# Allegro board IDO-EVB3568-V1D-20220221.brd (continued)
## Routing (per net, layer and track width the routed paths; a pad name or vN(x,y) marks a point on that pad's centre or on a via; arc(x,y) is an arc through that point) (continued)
USB2_HOST3_DM: length 39.3
  TOP w0.127: v2(71.75,67.19) 72,67.44 77.24,67.44 78.15,66.52 93.91,66.52 95,67.61 95.18,67.61 95.55,67.24 M5.101 ; L7.2 v2(72.94,79.18)
  BOTTOM w0.127: v2(71.75,67.19) 72,67.44 72.37,67.44 72.67,67.74 72.67,74.01 73.51,74.85 73.51,77.78 72.94,78.34 v2(72.94,79.18)
USB2_HOST3_DM_: length 14.8
  TOP w0.127: L7.3 72.94,81.59 72.67,81.86 72.67,82.32 72.83,82.49 72.83,82.91 72.96,83.04 D18.2 D18.9 72.96,84.91 72.83,85.03 72.83,85.41 72.16,86.08 70.38,86.08 68.33,88.13 68.33,89.31 68.78,89.76 69.27,89.76 70.84,91.34 J8.2
USB2_HOST3_DP: length 39.3
  TOP w0.127: v2(71.75,67.94) 72,67.69 77.34,67.69 78.26,66.78 91.77,66.78 91.9,66.9 92.28,66.9 92.41,66.78 92.79,66.78 92.91,66.9 93.29,66.9 93.42,66.78 93.8,66.78 94.89,67.86 95.18,67.86 95.55,68.24 M5.102 ; L7.1 72.14,79.27 72.2,79.21 v2(72.2,79.14)
  BOTTOM w0.127: v2(71.75,67.94) 72,67.69 72.26,67.69 72.42,67.84 72.42,74.12 73.25,74.96 73.25,77.67 72.64,78.28 72.64,78.69 v2(72.2,79.14)
USB2_HOST3_DP_: length 14.8
  TOP w0.127: J8.3 69.79,91.34 70.05,91.08 70.05,90.9 69.16,90.02 68.68,90.02 68.07,89.41 68.07,88.03 70.27,85.83 72.06,85.83 72.58,85.3 72.58,85.03 72.46,84.91 D18.10 D18.1 72.46,83.04 72.58,82.91 72.58,82.59 72.42,82.43 72.42,81.86 72.14,81.59 L7.4
USB3_HOST1_DM: length 45.8
  TOP w0.127: M5.182 36.46,47.24 36.83,46.86 37.09,46.86 38.23,48.01 38.23,50.04 39.24,51.05 47.7,51.05 48.01,50.75 48.01,50.41 v2(48.25,50.16)
  BOTTOM w0.127: v2(48.25,50.16) 48.01,50.41 48.01,76.48 49.04,77.51 L6.1
USB3_HOST1_DM_: length 10.4
  BOTTOM w0.127: L6.4 49.04,81.01 48.77,81.28 48.77,81.88 48.63,82.02 48.63,82.31 48.75,82.43 D15.6 D15.5 48.75,84.3 48.63,84.42 48.63,85.49 49.65,86.51 49.65,87.82 49.85,88.02 49.85,88.12 50.29,88.56 50.38,88.56 50.72,88.89 50.72,89.18 50.85,89.31 J5.11
USB3_HOST1_DP: length 45.8
  TOP w0.127: M5.183 36.46,46.24 36.83,46.61 37.19,46.61 38.48,47.9 38.48,49.93 39.35,50.8 47.6,50.8 47.75,50.64 47.75,50.41 v2(47.51,50.16)
  BOTTOM w0.127: v2(47.51,50.16) 47.75,50.41 47.75,76.58 48.79,77.62 48.79,78.57 48.74,78.62 48.74,78.62 48.69,78.66 48.44,78.66 48.24,78.86 L6.2
USB3_HOST1_DP_: length 10.4
  BOTTOM w0.127: L6.3 48.24,81.01 48.51,81.28 48.51,81.78 48.37,81.92 48.37,82.31 48.25,82.43 D15.7 D15.4 48.25,84.3 48.37,84.42 48.37,85.6 49.39,86.62 49.39,87.92 49.59,88.12 49.59,88.22 50.18,88.81 50.28,88.81 50.47,89 50.47,89.18 50.34,89.31 J5.12
USB3_HOST1_SSRXN: length 46.3
  TOP w0.127: R32.1 44.58,80.21 44.66,80.14 ; M5.185 36.11,44.24 36.27,44.4 36.91,44.4 39.88,47.37 46.08,47.37 v2(46.33,47.13) ; 44.66,80.14 C50.2 ; 44.66,80.14 44.78,80.01 v2(44.81,80.01)
  BOTTOM w0.127: v2(44.81,80.01) 44.96,79.86 44.96,76.96 45.59,76.33 45.59,47.62 45.84,47.37 46.08,47.37 v2(46.33,47.13)
USB3_HOST1_SSRXN_: length 9.6
  TOP w0.127: J5.14 47.34,87.81 47.47,87.68 47.47,86.74 46.96,86.23 45.47,86.23 44.82,85.59 44.82,84.37 44.7,84.25 D17.7 D17.4 44.7,82.63 44.88,82.45 44.88,81.51 R32.2
USB3_HOST1_SSRXP: length 46.3
  TOP w0.127: v2(46.33,47.87) 46.08,47.62 39.77,47.62 36.8,44.65 36.35,44.65 35.76,45.24 M5.184 ; R33.1 45.36,80.11 v2(45.36,80.01) 45.49,80.14 C51.2
  BOTTOM w0.127: v2(45.36,80.01) 45.21,79.86 45.21,77.07 45.85,76.43 45.85,47.73 45.95,47.62 46.08,47.62 v2(46.33,47.87)
USB3_HOST1_SSRXP_: length 9.6
  TOP w0.127: J5.15 47.85,87.81 47.72,87.68 47.72,86.64 47.07,85.98 45.57,85.98 45.07,85.48 45.07,84.37 45.2,84.25 D17.6 D17.5 45.2,82.53 45.14,82.47 45.14,81.66 R33.2
USB3_HOST1_SSTXN: length 49
  TOP w0.127: M5.181 35.79,48.24 36.16,48.61 36.7,48.61 37.34,49.25 37.34,50.55 38.81,52.02 49.5,52.02 49.81,51.71 49.81,51.4 v2(49.56,51.16)
  BOTTOM w0.127: v2(49.56,51.16) 49.73,51.16 50.05,51.48 50.05,75.94 53.54,79.43 53.54,80.57 53.31,80.8 C40.1
USB3_HOST1_SSTXN_: length 7.3
  BOTTOM w0.127: C40.2 53.47,82.01 53.47,82.42 53.23,82.66 D16.7 D16.4 53.23,84.3 53.35,84.42 53.35,86.35 53.47,86.47 53.47,87.68 53.34,87.81 J5.17
USB3_HOST1_SSTXP: length 49
  TOP w0.127: M5.180 35.8,49.24 36.18,48.86 36.59,48.86 37.08,49.36 37.08,50.65 38.71,52.27 49.61,52.27 50.06,51.82 50.06,51.4 v2(50.31,51.16)
  BOTTOM w0.127: v2(50.31,51.16) 50.31,75.83 53.8,79.32 53.8,80.42 C42.1
USB3_HOST1_SSTXP_: length 7.3
  BOTTOM w0.127: J5.18 53.85,87.81 53.72,87.68 53.72,86.36 53.61,86.25 53.61,84.42 53.73,84.3 D16.5 D16.6 53.73,82.01 54.08,81.66 C42.2
USB3_OTG0_DM: length 49.5
  TOP w0.127: M5.188 36.46,41.24 36.83,40.86 37.18,40.86 41.4,45.09 47.51,45.09 v2(47.75,45.33)
  BOTTOM w0.127: L5.1 47.26,78.66 47.07,78.46 46.84,78.46 46.72,78.33 46.72,77.8 47.07,77.45 47.07,45.21 47.22,45.06 47.48,45.06 v2(47.75,45.33)
USB3_OTG0_DM_: length 14.3
  BOTTOM w0.127: L5.4 47.26,81.36 46.99,81.64 46.99,81.92 47.13,82.06 47.13,82.55 47.25,82.67 D15.9 D15.2 47.25,84.3 47.13,84.42 47.13,86.25 47.75,86.87 47.75,88.39 48.49,89.13 48.49,89.26 49.6,90.37 49.6,91.15 50.2,91.75 50.38,91.75 50.72,92.09 50.72,92.38 50.85,92.51 J5.2
USB3_OTG0_DP: length 49.5
  TOP w0.127: M5.189 36.46,40.24 36.83,40.61 37.29,40.61 41.51,44.83 47.51,44.83 v2(47.75,44.59)
  BOTTOM w0.127: L5.2 46.46,77.69 46.81,77.34 46.81,45.11 47.11,44.81 47.53,44.81 v2(47.75,44.59)
USB3_OTG0_DP_: length 14.3
  BOTTOM w0.127: J5.3 50.34,92.51 50.47,92.38 50.47,92.2 50.28,92.01 50.1,92.01 49.35,91.26 49.35,90.47 48.23,89.36 48.23,89.23 47.5,88.5 47.5,86.97 46.88,86.35 46.88,84.42 46.75,84.3 D15.1 D15.10 46.75,82.67 46.88,82.54 46.88,82.16 46.74,82.02 46.74,81.64 46.46,81.36 L5.3
USB3_OTG0_SSRXN: length 50.9
  TOP w0.127: v2(42.66,79.91) 42.66,80.22 R30.1 ; v2(45.72,43.44) 45.48,43.69 42.04,43.69 36.96,38.61 36.59,38.61 36.22,38.24 M5.191
  BOTTOM w0.127: v2(45.72,43.44) 45.48,43.69 45.09,43.69 44.7,44.07 44.7,75.31 42.66,77.35 v2(42.66,79.91)
USB3_OTG0_SSRXN_: length 16.9
  TOP w0.127: R30.2 42.93,81.58 43.18,81.58 43.43,81.84 43.43,82.37 43.2,82.61 D17.1 D17.10 43.2,84.14 43.44,84.39 43.44,86.07 41.76,87.75 41.76,89.97 42.87,91.08 45.57,91.08 46.24,91.75 46.71,91.75 46.89,91.58 46.89,91.19 46.71,91.01 J5.5
USB3_OTG0_SSRXP: length 50.8
  TOP w0.127: v2(45.72,44.19) 45.48,43.94 41.93,43.94 36.85,38.86 36.59,38.86 36.22,39.24 M5.190 ; R31.1 43.41,80.19 v2(43.41,79.91)
  BOTTOM w0.127: v2(43.41,79.91) 43.21,79.71 43.05,79.71 42.92,79.58 42.92,77.46 44.96,75.42 44.96,44.17 45.19,43.94 45.48,43.94 v2(45.72,44.19)
USB3_OTG0_SSRXP_: length 17
  TOP w0.127: J5.6 47.8,91.01 47.04,90.25 46.2,90.25 45.62,90.83 42.98,90.83 42.01,89.87 42.01,87.86 43.7,86.17 D17.9 D17.2 43.7,81.72 43.56,81.58 R31.2
USB3_OTG0_SSTXN: length 52.6
  TOP w0.127: M5.187 36.22,42.24 36.59,42.61 37.02,42.61 40.64,46.23 48.64,46.23 48.9,45.97 48.9,45.71 v2(48.65,45.47)
  BOTTOM w0.127: v2(48.65,45.47) 48.9,45.71 48.9,76.45 51.51,79.07 51.51,80.21 51.28,80.44 51.11,80.44 C36.1
USB3_OTG0_SSTXN_: length 11.6
  BOTTOM w0.127: J5.8 53.34,91.01 53.47,90.88 53.47,90.12 51.56,88.21 51.56,87.03 51.85,86.74 51.85,84.42 51.73,84.3 D16.1 D16.10 51.73,82.54 50.85,81.66 C36.2
USB3_OTG0_SSTXP: length 52.6
  TOP w0.127: M5.186 36.22,43.24 36.59,42.86 36.92,42.86 40.53,46.48 48.75,46.48 49.15,46.08 49.15,45.71 v2(49.39,45.47)
  BOTTOM w0.127: v2(49.39,45.47) 49.15,45.71 49.15,76.35 51.77,78.96 C37.1
USB3_OTG0_SSTXP_: length 11.5
  BOTTOM w0.127: J5.9 53.85,91.01 53.72,90.88 53.72,90.01 51.82,88.11 51.82,87.14 52.11,86.85 52.11,84.42 52.23,84.3 D16.2 D16.9 52.23,82.69 51.54,82 51.54,81.82 51.7,81.66 C37.2
USB3_OTG0_VBUSDET: length 63.9
  TOP w0.127: v1(48.11,42.42) 41.91,42.42 36.73,37.24 M5.192 ; v2(55.75,80.14) 56.39,79.5 61.25,79.5 v2(61.95,80.21)
  BOTTOM w0.127: v1(48.11,42.42) 51.05,45.37 51.05,72.01 54.94,75.9 54.94,78.16 55.75,78.97 v2(55.75,80.14) ; v2(61.95,80.21) 61.95,80.29 61.98,80.32 61.98,80.72 R29.1
  BOTTOM w0.305: R29.1 R28.1
USB_OTG_PWREN_H: length 87.3
  TOP w0.127: v1(67.74,80.98) 68.07,80.64 68.07,75.69 68.45,75.31 70.31,75.31 70.68,74.94 72.63,74.94 73.15,74.42 88.49,74.42 89.26,73.66 94.03,73.66 99.57,68.12 99.57,62.99 100.97,61.59 100.97,53.59 102.36,52.2 102.36,49.78 97.54,44.96 97.54,44.2 97.92,43.81 97.92,33.4 97.28,32.77 97.28,27.69 96.83,27.24 M5.61
  BOTTOM w0.203: R34.1 66.37,80.98 U4.4
  BOTTOM w0.305: v1(67.74,80.98) 67.18,80.98 R34.1
VOLN: length 19.9
  TOP w0.381: J17.4 107.64,7.37 ; 107.64,7.37 107.26,7.75 v2(106.68,7.75) ; 107.64,7.37 107.64,9.09 108.33,9.78 108.33,11 D46.1 108.05,11.28 108.34,11.57 108.34,11.98 v2(108.18,12.14)
  BOTTOM w0.381: TP27.1 106.17,7.75 v2(106.68,7.75) ; v2(108.18,12.14) 108.36,11.97 108.36,11.4 108.84,10.92 109.88,10.92 110.52,11.56 110.52,14.33 109.66,15.18 108.22,15.18 C87.1 107.68,15.18 107.29,15.18 L17.2
VOLP: length 17.6
  TOP w0.381: v2(109.04,12.14) 108.85,11.95 108.85,11.6 D45.1 108.84,10.94 108.84,9.88 109.64,9.08 109.64,6.94 ; J17.3 109.64,6.94 ; 109.64,6.94 v2(108.84,7.75)
  BOTTOM w0.381: v2(108.84,7.75) 108.2,7.75 TP26.1 ; v2(109.04,12.14) 108.86,11.97 108.86,11.62 109.05,11.43 109.67,11.43 110.01,11.77 110.01,14.12 109.45,14.67 108.22,14.67 C88.1 107.68,14.67 107.29,14.67 L18.2
VORN: length 24.4
  TOP w0.381: 111.64,6.73 111.26,7.11 v2(110.74,7.11) ; 111.64,6.73 J17.2 ; 111.64,6.73 111.64,9.03 112.45,9.83 112.45,11.02 D44.1 112.43,11.52 112.43,12.01 v2(112.27,12.18)
  BOTTOM w0.381: TP25.1 108.97,5.33 v2(110.74,7.11) ; v2(112.27,12.18) 112.42,12.33 112.42,15.39 109.44,18.36 108.18,18.36 C90.1 107.72,18.36 107.25,18.36 L19.2
VORP: length 28.1
  TOP w0.381: J17.1 113.64,6.77 ; 113.64,6.77 113.3,7.11 v2(112.78,7.11) ; 113.64,6.77 113.64,9.17 112.95,9.86 112.95,11.02 D43.1 112.94,11.55 112.94,11.99 v2(113.13,12.18)
  BOTTOM w0.381: v2(112.78,7.11) 111.51,7.11 107.7,3.3 TP24.1 ; v2(113.13,12.18) 112.93,12.38 112.93,15.6 111.7,16.83 109.65,18.87 108.13,18.87 C91.1 107.82,18.92 107.2,18.92 L20.2
WIFI1T1R_CLK: length 20.2
  TOP w0.127: v2(112.01,62.71) 112.01,60.96 111.4,60.35 U23.17
  BOTTOM w0.127: R159.2 C153.2 101.17,57.66 108.08,57.66 109.83,59.41 109.83,59.97 109.73,60.07 109.22,60.07 109.09,60.2 109.09,60.45 109.22,60.58 109.73,60.58 109.82,60.67 109.82,61.18 111.35,62.71 v2(112.01,62.71)
WIFI1T1R_CMD: length 2.7
  TOP w0.127: R158.2 113.13,61.44 112.3,60.62 U23.16
WIFI1T1R_D0: length 2.7
  TOP w0.127: R153.2 110.74,61.72 111,61.47 111,60.71 110.5,60.21 U23.18
WIFI1T1R_D1: length 2.4
  TOP w0.127: U23.19 109.6,61.08 109.6,61.09 R154.2
WIFI1T1R_D2: length 3
  TOP w0.127: U23.14 114.1,60.94 R155.2
WIFI1T1R_D3: length 2.9
  TOP w0.127: U23.15 113.2,61.11 R156.2
WIFI1T1R_XTAL_IN: length 9.5
  TOP w0.203: XT3.3 120.85,62.2 120.85,59.92 C155.1 120.62,58.47 118.36,58.47 117.75,57.85 U23.10
WIFI1T1R_XTAL_OUT: length 3.4
  TOP w0.203: R163.2 119.76,58.83 118.18,58.83 118.11,58.75 U23.11
WIFI_REG_ON_H_GPIO3_D4: length 31.3
  TOP w0.127: R182.1 102.62,49.99 102.62,52.32 101.47,53.47 v2(101.47,53.95) ; v2(116.2,63.12) 116.3,63.22 R168.1 ; M5.91 96.81,57.24 100.1,53.95 v2(100.2,53.95)
  BOTTOM w0.127: v2(116.2,63.12) 116.2,62.74 108.71,55.24 104.52,55.24 103.38,54.1 102.11,54.1 101.96,53.95 v2(101.47,53.95) v2(100.2,53.95)
WIFI_WAKE_HOST_H_GPIO3_D5: length 23.9
  TOP w0.127: M5.90 97.23,56.24 v2(99.53,53.94) ; U23.13 v2(115,60.9)
  BOTTOM w0.127: v2(99.53,53.94) 99.93,53.54 102.06,53.54 102.36,53.85 103.5,53.85 104.65,54.99 108.97,54.99 114.88,60.9 v2(115,60.9)
WIFIBT_32KIN_1T1R: length 37.2
  TOP w0.127: U23.24 104.97,57.85 104.06,56.94 R176.2 C168.2 103.58,55.4 103.15,55.4 v2(102.87,55.12) ; R177.2 v2(113.28,43.54)
  BOTTOM w0.127: v2(102.87,55.12) 102.36,54.61 97.28,54.61 96.77,54.1 96.77,46.86 97.41,46.23 97.92,46.23 99.19,44.96 111.86,44.96 v2(113.28,43.54)
N17052705: length 1.5
  TOP w0.381: R179.1 104.23,53.35 U23.29
N17052995: length 4.9
  TOP w0.127: R181.2 104.04,49.43 R182.2 104.49,49.4 104.74,49.15 105.87,49.15 106.46,48.55 U23.34
N17053074: length 3.4
  TOP w0.508: C154.2 C156.2 U23.2
N17053234: length 2.6
  TOP w0.508: J29.2 C157.2 C154.1
N17053374: length 2.4
  TOP w0.127: R163.1 120.22,60.2 C158.2 119.2,60.5 119.02,60.68 XT3.1
N17846666: length 12
  TOP w0.127: v2(102.53,69.2) 102.13,69.6 102.13,70.97 98.3,74.8 98.3,76.76 R215.1
  BOTTOM w0.127: v2(102.53,69.2) 102.68,69.05 103.32,69.05 103.34,69.07 U24.31
N67123537: length 1.3
  BOTTOM w0.203: U4.3 66.06,84 R35.1
N67146313: length 8
  BOTTOM w0.254: R46.1 76.96,55.63 77.47,56.13 80.13,56.13 ; 80.13,56.13 80.9,56.13 81.13,56.37 U8.43 ; 80.13,56.13 U8.45
N67159131: length 1.5
  BOTTOM w0.127: R41.1 72.24,83.67 U6.3
N67228398: length 1.3
  TOP w0.305: C2.2 65,81.34 U1.4
N67228404: length 3.4
  TOP w0.254: R6.1 C8.1 ; C8.1 65.75,83.57 65.36,83.18 U1.6 ; C8.1 R4.2
N67928236: length 1.9
  TOP w0.381: U26.1 12.89,70.25 12.75,70.38 C218.2
N67928238: length 2.2
  TOP w0.381: C218.1 11.43,69.33 11.81,68.95 U26.3
N67928242: length 1.9
  TOP w0.381: U26.4 11.53,68.3 C219.2
N67928244: length 1.9
  TOP w0.381: C219.1 11.53,67.65 U26.5
N67928270: length 1.6
  TOP w0.127: U26.2 v2(14.22,69.6)
  BOTTOM w0.254: C220.2 13.76,69.6 v2(14.22,69.6)
N67928274: length 2.1
  TOP w0.381: C221.2 12.01,67 U26.6
N68112138: length 1.3
  TOP w0.381: R37.1 48.48,83.61 U5.3
N68117516: length 10.3
  TOP w0.127: R27.2 104.08,20.4 104.48,20.8 D12.1 106.93,20.8 108.94,18.8 111.76,18.8 112.01,18.54 J4.2
N68117520: length 6
  TOP w0.127: D10.C 105.42,18.28 106.02,17.68 D11.1 106.43,17.68 J4.1
N68117689: length 2.9
  TOP w0.127: D10.A 104.33,20.08 R26.2 R25.2
N68120764: length 6.9
  TOP w0.508: R84.1 v1(34.42,87.38) R82.1 ; D49.C v1(38.73,85.98)
  BOTTOM w0.508: v1(34.42,87.38) 35.81,85.98 v1(38.73,85.98)
N68141872: length 1.4
  BOTTOM w0.508: R115.1 40.71,31.24 40.74,31.26 U16.3
N68149060: length 2.9
  TOP w0.127: R62.2 142.16,99.19 SW1.1
N68226715: length 3.3
  TOP w0.127: U26.14 18.15,68.95 18.03,68.83 v2(17.65,68.83)
  BOTTOM w0.203: L34.1 17.02,68.2 v2(17.65,68.83)
N68226717: length 3.4
  TOP w0.127: v2(17.02,68.83) 17.56,68.3 U26.13
  BOTTOM w0.203: L35.1 16.74,68.83 v2(17.02,68.83)
N68226719: length 2
  TOP w0.203: U26.7 v2(14.27,66.34)
  BOTTOM w0.203: L36.1 14.81,66.34 v2(14.27,66.34)
N68226721: length 2
  TOP w0.203: U26.8 v2(14.32,65.69)
  BOTTOM w0.203: v2(14.32,65.69) 14.85,65.69 L37.1
N68234263: length 10.3
  TOP w0.254: J15.3 104.14,7.74 D38.1 104.09,13.67 R76.2
N68234265: length 5.8
  TOP w0.254: v2(95.41,10.03) 95.41,9.55 95.15,9.3 J15.2
  BOTTOM w0.254: 93.37,10.95 93.37,10.64 93.98,10.03 v2(95.41,10.03) ; 93.37,10.95 93.66,10.95 93.71,11 R73.2 ; 93.37,10.95 D40.1
N68234885: length 2.2
  TOP w0.254: C80.2 R68.2 R69.1
N68235937: length 4.1
  TOP w0.254: J15.5 95.25,12.75 D39.1 95.3,13.9 R74.2
N68290667: length 2.4
  BOTTOM w0.381: U13.1 104.09,14.43 104.37,14.71 104.81,14.71 L18.1
N68290669: length 5.1
  BOTTOM w0.381: U13.3 101.55,14.43 102.36,15.24 104.91,15.24 L17.1
N68290717: length 5
  BOTTOM w0.381: L19.1 104.96,18.29 102.49,18.29 101.55,19.23 U13.14
N68290719: length 2.2
  BOTTOM w0.381: L20.1 104.89,18.92 104.39,18.92 104.09,19.23 U13.16
N68290721: length 1
  BOTTOM w0.254: C86.1 R79.1
N68290723: length 1.9
  BOTTOM w0.254: R79.2 96.52,12.35 96.47,12.4 U13.7
N68290736: length 1.1
  TOP w0.254: R80.1 C89.1
N68290738: length 7
  TOP w0.254: R80.2 100.58,14.63 v2(96.9,18.31)
  BOTTOM w0.254: v2(96.9,18.31) 96.47,18.75 U13.10
N68290823: length 1.7
  TOP w0.254: v2(94.49,13.21) 94.11,13.59 C85.2
  BOTTOM w0.254: v2(94.49,13.21) 95,13.72 U13.8
N68391184: length 1.6
  BOTTOM w0.508: U2.1 32.59,49.51 32.77,49.68 R14.2
N68391239: length 3.6
  BOTTOM w0.508: C19.1 R12.2 R15.1 29.72,49.68 29.89,49.51 U2.5
N68444772:
  vias: v1(14.35,83.67) v1(14.35,83.01) v1(14.99,83.67) v1(14.99,82.98) v1(15.72,83.67) v1(15.75,82.96) v1(16.48,82.58) v1(17.02,82.58) v1(17.78,83.64) v1(17.81,82.91)
N68540703: length 37.4
  TOP w0.127: v2(113.85,67.37) 113.57,67.65 113.57,67.66 113.03,68.2 113.03,73.68 111.66,75.06 103.3,75.06 101.98,76.38 v2(101.98,76.48)
  BOTTOM w0.127: U25.31 117.73,67.39 117.65,67.31 114.93,67.31 114.87,67.37 v2(113.85,67.37) ; v2(101.98,76.48) 101.5,76.96 97.66,76.96 96.39,75.69 96.39,70.48 95.12,69.22 R262.1
N68550545: length 3
  TOP w0.305: U17.11 27.95,24.81 C129.2
  TOP w0.381: C126.2 C129.2
N68551303: length 3.6
  TOP w0.127: U17.8 26.68,23.31 27.08,22.91 27.08,21.87 27.64,21.31 R121.2
N68551306: length 2.3
  TOP w0.127: R122.2 27.62,25.31 U17.12
N68551396: length 3.6
  TOP w0.127: R120.2 26.72,21.67 26.72,22.48 26.39,22.81 U17.7
N68552374: length 7.2
  TOP w0.508: R131.2 R129.2 45.54,13.76 45.27,14.03 C141.1 43.37,14.03 42.55,13.21 41.59,13.21 41.09,12.7 Q9.1
N68552446: length 1.8
  TOP w0.254: R131.1 47.5,12.91 47.87,12.54 Q10.3
N68558276: length 1.1
  TOP w0.305: U15.3 12.65,22.84 R104.1
N68563618: length 5
  TOP w0.203: U34.1 123.63,41.34 C239.1 124.06,41.53 125.48,41.53 125.68,41.33 XT6.1
N68563661: length 5
  TOP w0.203: U34.2 123.4,41.99 C240.1 124.11,41.99 125.43,41.99 125.68,42.24 XT6.2
N68582360: length 14.8
  TOP w0.127: Q6.1 79.17,13.02 78.74,13.45 78.74,15.75 79.38,16.38 83.95,16.38 84.71,15.62 R90.2 85.58,14.4 C111.1 85.98,15.36 86.41,15.8 R91.2
N68582430: length 1.8
  TOP w0.381: R91.1 87.25,14.19 87.47,13.97 Q7.3
N68600227: length 4.4
  TOP w0.127: R326.1 111.86,37.29 111.28,36.7 110.62,36.7 109.45,35.54 J41.10
N68600229: length 5.2
  TOP w0.127: J41.12 110.25,35.45 111,36.2 112.62,36.2 113.28,36.86 R327.1
N68600231: length 4.1
  TOP w0.127: J41.14 111.05,35.36 111.38,35.69 v2(112.14,35.69)
  BOTTOM w0.127: v2(112.14,35.69) 112.53,35.69 112.9,35.32 R329.1
N68600309: length 2.8
  TOP w0.381: J41.8 108.65,37.01 L48.1
N68610828: length 1.5
  TOP w0.381: Q12.1 125.51,58.61 125.43,58.52 R178.2
N68611164: length 2.3
  TOP w0.254: R178.1 126.96,57.78 127.64,57.11 Q13.3
N68644173: length 2.7
  TOP w0.127: R168.2 115.9,61.52 U23.12
N68693421: length 1.4
  TOP w0.381: U7.3 76.72,80.96 76.71,80.98 R43.1
N68696061: length 1.6
  BOTTOM w0.381: R49.1 89.84,79.62 U9.3
N68696295: length 1.4
  TOP w0.381: R53.1 92.53,78.02 U10.3
N68706836: length 1.6
  TOP w0.127: R57.1 137.08,47.67 136.73,47.32 U11.3
N68707388: length 1.6
  TOP w0.203: R59.1 137.94,66.5 137.83,66.61 U12.3
N68721096: length 3.9
  TOP w0.127: v2(111.89,32.89) 110.44,31.45 U36.66
  BOTTOM w0.127: R325.2 v2(111.89,32.89)
N68721887: length 1.7
  TOP w0.254: R342.2 106.17,42.16 106.75,41.59 U37.1
N68721933: length 3.3
  TOP w0.381: R340.2 C265.1 109.5,42.62 R341.1 109.55,42.65 109.66,42.54 U37.5
N68723170: length 4.3
  TOP w0.305: v2(125.94,31.62) 125.74,31.62 125.44,31.32 U36.6
  BOTTOM w0.254: R337.2 R338.1 C252.2 v2(125.94,31.62)
N68753609: length 2.1
  BOTTOM w0.127: U35.24 65.01,36.59 64.03,35.61 R321.2
N68753612: length 2.2
  BOTTOM w0.127: R322.1 67.03,35.61 65.81,36.83 U35.22
N68753720: length 1.8
  BOTTOM w0.127: R320.2 65.02,36.24 65.41,36.63 U35.23
N68753740: length 3.1
  BOTTOM w0.127: U35.12 67.01,40.9 67.13,41.02 67.69,41.02 TP1.1
N68754791: length 2.3
  BOTTOM w0.127: C245.2 67.41,41.86 66.95,41.4 66.42,41.4 66.21,41.2 U35.10
N68764417: length 4.4
  TOP w0.254: L3.1 26.29,48.49 U39.2
  TOP w0.381: v1(28.73,50.27) 28.73,50.9 C16.1
  BOTTOM w0.381: v1(28.73,50.27) v1(28.73,48.74)
N68764421: length 1.1
  TOP w0.254: C16.2 27.87,50.91 U39.4
N68764430: length 3.7
  TOP w0.254: R13.2 C24.1 R17.1 25.4,52.07 25.79,51.68 U39.6
N68782340: length 1.6
  BOTTOM w0.508: U19.3 33.46,61.15 33.66,60.96 R149.2
N68782427: length 1.7
  BOTTOM w0.508: U20.3 33.46,57.47 33.78,57.15 R150.2
N68782451: length 1.8
  BOTTOM w0.254: R151.2 34.11,53.11 33.44,53.79 U21.3
N68784083: length 2.3
  TOP w0.305: R78.1 135.68,20.24 135.76,20.32 C83.2 R75.2
N68821934: length 18.1
  BOTTOM w0.127: R8.2 23.24,83.11 23.24,89.2 21.86,90.59 21.85,90.59 21.07,91.36 21.07,91.37 18.92,93.52 18.92,95.94 LED1.1
N68821936: length 15.1
  BOTTOM w0.127: R9.2 23.62,82.3 22.99,82.93 22.99,89.05 17.88,94.16 LED1.3
N68825811: length 1.6
  TOP w0.254: LED2.A 131.74,19.14 131.37,19.51 R334.2
N68865571: length 4.8
  BOTTOM w0.254: U28.2 R288.2 20.01,58.09 20.48,57.62 D84.A 21.78,57.62 C227.2
N68866830: length 4.3
  BOTTOM w0.254: 18.42,49.02 18.42,49.77 18.55,49.91 D88.A 17.83,51.4 R295.2 ; 18.42,49.02 U30.2 ; 18.42,49.02 C230.2
N68869057: length 1.9
  TOP w0.381: U27.1 11.57,63.54 C223.2
N68869059: length 2.1
  TOP w0.381: C223.1 12.01,62.24 U27.3
N68869063: length 1.9
  TOP w0.381: U27.4 11.53,61.59 C224.2
N68869065: length 1.9
  TOP w0.381: U27.5 11.53,60.94 C224.1
N68869069: length 1.5
  TOP w0.381: U27.2 v2(14.2,62.89)
  BOTTOM w0.381: C225.2 14.17,62.87 v2(14.2,62.89)
N68869073: length 2.1
  TOP w0.381: C226.2 12.01,60.29 U27.6
N68869089: length 2
  TOP w0.127: v2(17.78,62.74) 18.28,62.24 U27.14
  BOTTOM w0.127: L38.1 v2(17.78,62.74)
N68869091: length 1.9
  TOP w0.127: U27.13 18.03,61.59 v2(17.78,61.34)
  BOTTOM w0.127: L39.1 v2(17.78,61.34)
N68869093: length 2
  TOP w0.127: U27.7 v2(14.3,59.64)
  BOTTOM w0.127: v2(14.3,59.64) 13.99,59.94 L40.1
N68869095: length 1.9
  TOP w0.127: U27.8 v2(14.22,58.99)
  BOTTOM w0.127: v2(14.22,58.99) 13.91,58.67 L41.1
N68871128: length 2.7
  BOTTOM w0.381: R303.2 20.75,41.61 21.11,41.25 C235.2
  BOTTOM w0.508: R304.2 R303.2
N68871171: length 2.7
  TOP w0.381: U32.5 13.91,44.02 C234.2 R300.2
N68877118: length 2.8
  BOTTOM w0.381: C238.2 20.44,35.94 R311.2 R310.2
N68877190: length 3.3
  TOP w0.381: U33.5 13.53,38.48 12.79,37.74 12.27,37.74 R367.2 C237.2
N68886075: length 7.8
  TOP w0.508: J31.1 133.88,84.58 134.09,84.38 136.07,84.38 138.1,86.41 C202.2
N68888039: length 6.2
  TOP w0.508: v1(112.9,80.14) 113.92,81.15 J30.1
  BOTTOM w0.508: v1(112.9,80.14) 112.39,79.63 C179.2
N69126369: length 3.3
  TOP w0.127: J41.22 117.45,35.48 117.47,35.5 R376.1
N69153757: length 14.5
  TOP w0.203: U39.5 26.29,51.31 26.54,51.56 27.81,51.56 28.19,51.94 28.19,52.96 28.5,53.26 C12.2
  TOP w0.254: R3.2 R5.1 23.45,54.05 24,54.61 28.45,54.61 28.83,54.23 C12.2
N69164567: length 2.1
  TOP w0.152: U1.5 65.53,82.68 65.66,82.55 65.66,82.02 66.25,81.43 R16.2
N69167857: length 1.6
  TOP w0.127: R381.1 137.08,57.58 136.73,57.23 U40.3
N69206132: length 9
  BOTTOM w0.305: 26.16,64.29 R386.1 ; 26.16,64.29 R389.2 ; 26.16,64.29 28.55,64.29 29.08,63.75 30.73,63.75 31.11,63.37 31.11,62.13 30.14,61.15 U19.4
N69206262: length 3.9
  TOP w0.381: v1(28.37,57.28) 28.17,57.48 R387.2 R388.1 C492.2
  BOTTOM w0.305: v1(28.37,57.28) 29.7,57.28 U20.4
N69206971: length 5.2
  BOTTOM w0.305: U21.4 29.83,53.72 27.69,53.72 26.99,54.42 26.67,54.42 26.14,54.94 R390.1 R391.2

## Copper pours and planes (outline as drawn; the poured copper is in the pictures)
GND on TOP (solid shape): 130.11,18.95 130.11,17.79 130.01,17.69 129.37,17.69 129.37,19.1 129.96,19.1
GND on TOP (solid shape): 103.44,23.29 103.44,21.7 103.17,21.7 103.17,19.96 103.69,19.96 103.79,19.9 103.77,19.79 103.75,19.77 102.88,19.77 102.88,20.45 102.55,20.78 102.55,21.26 102.93,21.64 102.93,23.59 102.72,23.8 102.77,23.85 102.86,23.87
GND on TOP (solid shape): 101.28,24.19 101.33,24.28 101.43,24.28 101.56,24.25 101.69,24.25 101.72,24.26 102.55,23.43 102.55,21.8 102.17,21.41 102.17,20.62 102.5,20.29 102.5,19.77 102.26,19.77 102.26,18.84 103.36,18.84 103.36,18.62 102.26,18.62 102.26,18.48 102.01,18.48 101.98,18.45 99.7,18.45 98.32,19.83 98.3,19.93 98.37,20 101.28,22.91
GND on TOP (solid shape): 112.43,35.36 112.46,35.32 112.46,32.18 113.17,31.47 113.19,31.36 113.1,31.29 110.63,31.29 110.63,31.37 111.77,32.5 111.79,32.5 112.18,32.61 112.28,32.99 112.28,33.06 112.31,33.06 112.31,35.32 112.34,35.34 112.38,35.36
GND on TOP (solid shape): 122.59,32.19 122.59,32.18 122.62,32.07 122.68,31.97 122.68,29.88 122.47,29.67 122.36,29.65 122.3,29.74 122.3,31.29 121.91,31.29 121.83,31.33 121.81,31.41 121.7,31.79 121.32,31.89 121.29,31.89 120.97,32.21 120.94,32.32 121.04,32.38 122.4,32.38
GND on TOP (solid shape): 21.44,18.45 21.54,18.39 21.51,18.28 18.75,15.52 17.05,15.52 16.02,14.49 16.02,13.95 15.85,13.78 15.74,13.78 15.74,11.82 16,11.82 16,11.37 15.33,10.69 14.56,10.69 13.82,9.95 13.82,9.84 13.75,9.84 13.73,9.85 13.09,10.04 12.49,9.74 12.47,9.73 12.4,9.73 12.4,9.86 13.56,11.02 14.63,11.02 15.09,11.48 15.09,11.82 15.35,11.82 15.35,13.78 15.22,13.78 15.22,13.8 15.12,13.91 16.91,15.7 18.69,15.7 21.35,18.35 21.35,18.45
GND on TOP (solid shape): 23.44,18.45 23.54,18.39 23.51,18.28 19.07,13.83 19.07,13.78 18.79,13.78 18.79,11.82 18.91,11.82 18.91,11.8 19.05,11.67 19.05,11.05 19.89,10.21 19.89,9.94 19.83,9.84 19.72,9.86 19.16,10.05 18.61,9.85 18.5,9.84 18.44,9.93 18.44,11.34 18.13,11.65 18.13,11.67 18.29,11.82 18.4,11.82 18.4,13.78 18.14,13.78 18.14,14.17 19.23,14.17 23.35,18.3 23.35,18.45
GND on TOP (solid shape): 116.84,37.95 116.95,37.97 117.01,37.88 117.01,37.1 117.28,37.1 117.28,35.58 117.26,35.56 117.26,35.49 116.19,35.49 116.19,33.35 116.16,33.27 116.09,33.24 115.88,33.2 115.71,33.07 115.62,33.04 115.54,33.09 115.25,33.29 114.91,33.19 114.87,33.17 114.84,33.19 114.79,33.22 114.74,33.25 114.74,34.85 116.01,36.12 116.01,36.67 116.18,36.67 116.18,37.66 116.43,37.91 116.8,37.91
GND on TOP (solid shape): 27.74,14.08 27.82,14.05 27.97,13.94 28.14,13.91 28.18,13.89 28.19,13.86 28.19,13.78 27.93,13.78 27.93,11.82 28.19,11.82 28.19,11.62 28.53,11.28 32.41,11.28 33.5,10.19 33.52,10.06 33.41,10.02 32.97,10.03 32.58,9.83 32.47,9.82 32.41,9.91 32.41,10.33 31.64,11.1 27.86,11.1 27.29,11.67 27.43,11.82 27.54,11.82 27.54,13.78 27.28,13.78 27.28,13.84 27.29,13.87 27.33,13.89 27.52,13.93 27.67,14.04
GND on TOP (solid shape): 80.01,38.37 80.09,38.34 80.14,38.29 80.2,38.25 80.2,33.81 80.17,33.8 79.98,33.23 80.55,33.08 80.66,33.08 80.71,32.99 80.71,31.7 79.11,30.11 79.06,30.12 79.03,30.14 79.02,30.18 79.02,30.25 79.01,30.32 79,30.35 79.31,30.66 79.31,38.15 79.36,38.23 79.46,38.24 79.71,38.21 79.93,38.34
GND on TOP (solid shape): 127.99,20.02 128.05,20 128.12,19.99 128.15,19.97 128.16,19.94 128.16,19.1 128.79,19.1 128.99,18.9 128.99,17.84 128.84,17.69 128.11,17.69 128.11,16.95 128.09,16.94 127.98,16.91 127.92,17.01 127.92,17.69 126.89,17.69 126.85,17.62 126.78,17.6 126.34,17.2 126.78,16.79 126.85,16.77 126.89,16.71 127.22,16.71 127.22,16.54 126.54,15.86 126.54,15.85 126.51,15.83 126.37,15.75 126.27,15.63 126.18,15.58 126.1,15.63 126.06,15.67 126.01,15.73 126.01,15.9 126.08,15.97 126.08,16.63 126.19,16.63 126.19,17.57 126.3,17.69 126.3,17.76 126.5,17.76 126.5,19.07 126.12,19.07 125.89,19.3 125.87,19.43 126.6,19.43 126.85,19.68 127.61,19.68 127.85,19.92 127.85,19.93 127.96,20.03
GND on TOP (solid shape): 84.84,38.47 84.84,38.46 85.13,38.21 85.49,38.31 85.6,38.33 85.66,38.23 85.66,38.21 85.62,38.13 85.54,38.12 85.06,37.86 85.26,37.36 85.26,35.49 79.45,29.68 79.4,29.73 79.38,29.84 81.09,31.54 81.09,40.15 81.19,40.23 81.26,40.33 81.34,40.38 81.42,40.35 81.47,40.31 81.47,38.34 81.66,37.58 81.85,38.34 81.85,38.53 81.9,38.61 82,38.62 82.53,38.81 82.36,39.35 82.36,40.72 81.54,41.54 81.56,41.64 81.61,41.69
GND on TOP (solid shape): outline of 112 points within 108.96,32.12 122.98,43.75
GND on TOP (solid shape): outline of 84 points within 76.06,29.02 81.98,50.21
GND on TOP (solid shape): outline of 115 points within 19.65,18.64 26.53,25.46
GND on BOTTOM (solid shape): 144.61,8.14 144.72,8.17 144.78,8.07 144.78,1.27 144.5,0.59 143.81,0.3 137.01,0.3 136.92,0.37 136.94,0.48 138.77,2.31 138.8,2.29 142.18,2.9 142.79,6.28 142.78,6.31
GND on BOTTOM (solid shape): 71.18,24.21 71.21,24.26 71.27,24.25 71.37,24.15 71.37,23.42 72.1,23.42 72.97,22.55 72.96,22.53 72.96,20.85 75.67,20.85 75.67,22.53 75.6,22.53 75.6,22.62 75.81,22.83 76.57,22.83 76.84,23.11 77.42,23.11 77.42,21.18 78.49,20.11 78.49,16.5 84.82,10.16 84.82,9.92 84.81,9.91 84.66,9.75 84.55,9.57 84.46,9.51 83.46,10.15 82.46,9.51 82.37,9.57 82.28,9.73 81.84,10.18 81.84,11.16 79.28,13.72 74.2,13.72 71.21,16.7 71.21,16.72 70.92,17.08 70.46,17.03 70.45,17.02 70.39,17.02 70.1,17.3 70.1,21.81 70.18,21.89 70.28,21.92 70.35,21.85 70.85,21.58 71.13,22.06 71.13,22.09 71.18,22.15
GND on GND (solid shape): 144.61,8.14 144.72,8.17 144.78,8.07 144.78,1.27 144.5,0.59 143.81,0.3 137.01,0.3 136.92,0.37 136.94,0.48 138.77,2.31 138.8,2.29 142.18,2.9 142.79,6.28 142.78,6.31
GND on TOP: 0.3,100.84 0.59,101.52 1.27,101.8 143.81,101.8 144.5,101.52 144.78,100.84 144.78,1.27 144.5,0.59 143.81,0.3 100.13,0.3 100.13,1.52 96.16,1.52 96.16,0.3 1.27,0.3 0.59,0.59 0.3,1.27 ; 132 cut-outs
GND on BOTTOM: 0.3,100.84 0.59,101.52 1.27,101.8 143.81,101.8 144.5,101.52 144.78,100.84 144.78,1.27 144.5,0.59 143.81,0.3 100.13,0.3 100.13,1.52 96.16,1.52 96.16,0.3 1.27,0.3 0.59,0.59 0.3,1.27 ; 113 cut-outs
GND on VCC: 0.3,100.84 0.59,101.52 1.27,101.8 143.81,101.8 144.5,101.52 144.78,100.84 144.78,1.27 144.5,0.59 143.81,0.3 100.13,0.3 100.13,1.52 96.16,1.52 96.16,0.3 1.27,0.3 0.59,0.59 0.3,1.27 ; 3 cut-outs
GND on GND: 0.3,100.84 0.59,101.52 1.27,101.8 143.81,101.8 144.5,101.52 144.78,100.84 144.78,1.27 144.5,0.59 143.81,0.3 100.13,0.3 100.13,1.52 96.16,1.52 96.16,0.3 1.27,0.3 0.59,0.59 0.3,1.27
GND_EARTH on TOP: 140.21,93.34 140.59,92.96 140.59,88.27 140.08,87.76 135.51,87.76 134.75,88.52 134.75,90.68 137.41,93.34
GND_IN on TOP: 19.3,92.46 14.48,92.46 13.59,93.34 13.59,96.14 13.08,96.65 5.59,96.65 4.57,95.63 4.57,89.28 5.84,88.01 10.19,88.01 13.84,84.35 20.09,84.35 20.27,84.53 20.27,91.49
GND_IN on BOTTOM: 5.21,95.63 15.75,95.63 20.32,91.06 20.32,86.49 20.07,86.23 15.88,86.23 15.75,86.36 15.75,89.79 14.1,91.44 5.21,91.44 4.7,91.95 4.7,95.12
GND_IN on BOTTOM: 6.4,79.45 9.14,76.71 9.14,75.06 9.02,74.93 5.97,74.93 5.71,75.18 5.71,75.95 4.45,77.22 4.45,78.71 5.18,79.45
GND_IN on GND: 15.75,95.63 4.7,95.63 4.7,74.8 10.72,74.8 11.02,75.11 11.02,82.98 12.65,84.61 19.15,84.61 20.32,85.78 20.32,91.06
VBAT_WL_1T1R on TOP: 123.29,63.86 124.21,63.86 124.51,63.55 124.51,59.74 124.46,59.69 124.46,59.31 123.57,58.42 123.57,57.78 123.58,57.77 123.58,57.52 123.06,57 119.48,57 119.02,56.54 116.59,56.54 116.43,56.69 116.43,57.15 116.59,57.3 118.57,57.3 119.18,57.91 121.31,57.91 122.53,59.13 122.53,60.66 122.99,61.11 122.99,63.55
VCC1V5_DVP on BOTTOM: 30.35,58.93 30.48,59.05 30.48,59.69 30.1,60.07 29.34,60.07 28.83,60.58 27.18,60.58 26.67,60.07 26.67,59.05 26.8,58.93
VCC1V8_DVP on BOTTOM: 25.15,60.96 25.53,60.96 25.78,61.21 25.78,62.1 26.29,62.61 30.35,62.61 30.48,62.74 30.48,63.37 30.35,63.5 28.96,63.5 28.83,63.63 25.27,63.63 24.64,62.99 24.64,61.85 24.21,61.42 24.21,60.71 23.44,59.94 23.44,59.08 24.56,59.08 24.77,59.28 24.84,59.28 25.02,59.46 25.02,59.87 24.94,59.94 24.94,60.76
VCC2V8_DVP on TOP: 27.48,57.43 27.15,57.43 26.37,58.22 25.27,58.22 24.89,58.6 23.42,58.6 23.34,58.52 23.34,57.94 23.55,57.73 24.74,57.73 25.12,57.35 26.21,57.35 26.21,57.33 26.8,56.74 26.8,55.98 27.38,55.4 27.81,55.4 28.17,55.75 28.17,56.82 28.04,56.95 27.89,56.95 27.48,57.35
VCC2V8_DVP on BOTTOM: 30.48,55.37 30.61,55.5 30.61,56.01 30.18,56.44 29.18,56.44 28.91,56.72 27.13,56.72 26.67,56.26 26.67,55.5 26.8,55.37
VCC3V3_PHY0 on VCC: 100.71,70.89 100.52,71.07 100.52,71.93 102.44,73.85 103.81,73.85 104.08,73.58 104.08,73.1 103.31,72.34 103.31,71.68 103.68,71.31 105.71,71.31 106.49,70.53 106.49,68.37 107.11,67.75 109.43,67.75 109.92,68.25 109.92,73.58 110.31,73.98 111.05,73.98 112.46,72.57 112.46,66.1 112.47,66.09 112.47,64.06 101.9,64.06 100.61,65.35 100.61,66.67 100.46,66.83 100.46,70.61 100.71,70.86
VCC3V3_PHY1 on VCC: 112.85,65.72 115.78,65.72 116.52,66.47 116.52,67.36 116.92,67.75 120.83,67.75 122.98,65.6 123.78,65.6 124.14,65.96 124.14,69.8 122.62,71.33 122.62,72.21 122,72.83 119.43,72.83 118.81,72.21 118.81,71.71 118.54,71.44 117.45,71.44 117.37,71.51 117.37,73.79 124.48,73.79 124.48,73.79 125.05,73.79 126.36,72.47 126.36,64.77 126.11,64.52 117.98,64.52 117.6,64.14 112.85,64.14
VCC5V0_SYS on TOP: 109.09,40.77 110.11,40.77 111.38,42.04 112.27,42.04 112.39,41.91 112.39,39.37 112.14,39.12 109.22,39.12 108.97,39.37 108.97,40.64
VCC5V0_SYS on TOP: 74.17,13.72 73.03,13.72 72.64,13.34 72.01,13.34 71.88,13.21 71.88,12.06 72.01,11.94 73.91,11.94 74.3,12.32 74.3,13.59
VCC5V0_SYS on TOP: 32,15.49 32,13.46 32.13,13.34 33.15,13.34 33.27,13.46 33.27,14.1 33.53,14.35 35.69,14.35 35.94,14.61 35.94,14.86 35.81,14.99 35.18,14.99 34.67,15.49 33.02,15.49 32.89,15.62 32.13,15.62
VCC5V0_SYS on TOP: 37.34,22.73 37.08,22.99 37.08,24.13 37.34,24.38 37.85,24.38 37.97,24.51 37.97,26.42 38.23,26.67 39.62,26.67 39.75,26.54 39.75,22.99 39.5,22.73
VCC5V0_SYS on TOP: 20.7,44.32 21.62,44.32 21.87,44.07 21.87,42.82 21.08,42.04 18.26,42.04 15.06,38.84 13.08,38.84 12.55,38.3 11.89,38.3 11.73,38.15 11.73,37.49 11.66,37.41 10.52,37.41 10.52,34.11 9.98,33.58 8.89,33.58 8.41,34.06 8.41,38.38 8.51,38.48 8.53,38.48 8.53,39.37 9.22,40.06 14.86,40.06 14.88,40.03 17.2,42.34 17.2,43.59 17.35,43.74 20.17,43.74 20.7,44.27
VCC5V0_SYS on TOP: 14.68,29.01 15.34,29.01 16.84,27.51 16.84,25.7 16.66,25.53 14.81,25.53 14.66,25.68 14.66,28.98
VCC5V0_SYS on TOP: 28.83,45.85 28.96,45.72 28.96,43.94 29.21,43.69 30.86,43.69 31.37,43.18 31.37,41.15 31.24,41.02 24.08,41.02 23.72,41.38 23.72,45.19 24.38,45.85
VCC5V0_SYS on BOTTOM: 33.66,14.73 33.58,14.81 33.58,15.93 33.91,16.26 36.96,16.26 38.1,17.4 38.1,26.16 39.12,27.18 40.26,27.18 40.39,27.05 40.39,16.89 38.25,14.76 37.31,14.76 37.29,14.73
VCC5V0_SYS on BOTTOM: 102.62,23.75 102.49,23.62 102.49,22.73 102.62,22.61 103.63,22.61 104.01,22.23 104.01,21.59 104.14,21.46 104.9,21.46 105.03,21.59 105.03,22.23 103.5,23.75
VCC5V0_SYS on BOTTOM: 29.21,47.12 29.34,47.24 30.73,47.24 32.26,45.72 32.26,42.16 31.24,41.15 29.72,41.15 29.59,41.27 29.59,46.23 29.21,46.61
VCC5V0_SYS on BOTTOM: 42.93,35.26 42.93,33.53 43.31,33.15 48.51,33.15 48.77,33.4 48.77,36.2 48.51,36.45 45.47,36.45 44.96,35.94 43.61,35.94
VCC5V0_SYS on VCC: 32.64,33.27 19.68,33.27 18.03,31.62 17.02,31.62 16.26,30.86 16.26,27.84 16.76,27.33 16.76,26.29 16.64,26.16 15.49,26.16 15.32,26.34 15.32,28.57 14.83,29.06 14.83,32.08 15.16,32.41 16.28,32.41 18.54,34.67 18.54,37.72 20.95,40.13 20.95,42.93 20.83,43.05 20.83,43.43 20.95,43.56 31.11,43.56 32.26,42.42 32.26,40.26 34.42,38.1 46.48,38.1 53.34,31.24 53.34,26.54 54.74,25.15 67.06,25.15 67.94,24.26 77.47,24.26 77.6,24.38 77.6,24.89 77.72,25.02 78.49,25.02 78.61,24.89 78.61,24.51 78.87,24.26 99.31,24.26 102.11,27.05 102.11,41.66 103.63,43.18 111.12,43.18 112.39,41.91 112.39,39.37 112.27,39.24 111.51,39.24 111.12,38.86 111.12,37.47 111,37.34 105.92,37.34 104.39,35.81 104.39,33.66 108.46,29.59 108.46,23.75 104.01,19.3 89.79,19.3 89.15,19.94 86.36,19.94 85.47,19.05 84.2,19.05 83.31,19.94 67.69,19.94 65.79,21.84 60.83,21.84 59.82,22.86 50.67,22.86 49.28,24.26 38.61,24.26 37.59,25.27 37.59,34.67 37.08,35.18 34.54,35.18
VCC5V0_USB_FE_D1 on TOP: 74.42,88.01 76.33,86.11 78.74,86.11 79.38,85.47 79.38,83.95 79.25,83.82 78.99,83.82 78.87,83.69 78.87,82.68 78.74,82.55 77.6,82.55 77.47,82.68 77.47,84.07 77.34,84.2 76.45,84.2 73.03,87.63 73.03,87.88 73.15,88.01
VCC5V0_USB_FE_D2 on TOP: 90.88,81.97 91.49,81.97 91.77,82.25 91.77,85.57 91.26,86.08 91.26,89.81 92,90.55 92.68,90.55 92.84,90.7 92.84,91.9 92.61,92.13 91.39,92.13 90.4,91.14 90.4,83.49 90.37,83.46 90.37,82.88 90.63,82.63 90.63,82.22
VCC5V0_USB_FE_D2 on BOTTOM: 88.27,82.22 89.99,82.22 90.12,82.09 92.61,82.09 92.86,82.35 92.86,83.06 92.68,83.24 88.37,83.24 88.06,82.93 88.06,82.42
VCC5V0_USB_FE_D3 on TOP: 91.57,86.21 92.02,85.75 92.02,82.78 91.95,82.7 91.95,80.9 93.09,80.9 93.22,81.03 93.22,82.17 93.47,82.42 94.11,82.42 94.23,82.55 94.23,85.34 92.84,86.74 92.84,87.88 92.71,88.01 91.69,88.01 91.57,87.88
VCC5V0_USB_FE_D4 on TOP: 137.79,42.67 137.92,42.55 142.62,42.55 143.64,43.56 143.64,45.97 143.26,46.35 140.97,46.35 139.95,45.34 136.27,45.34 136.14,45.21 136.14,44.58 136.27,44.45 137.54,44.45 137.79,44.2
VCC5V0_USB_FE_D5 on TOP: 137.92,52.58 140.34,52.58 143.51,55.75 143.51,56.77 143.26,57.02 141.1,57.02 139.45,55.37 136.14,55.37 136.02,55.24 136.02,54.61 136.14,54.48 137.41,54.48 137.79,54.1 137.79,52.7
VCC5V0_USB_FE_D6 on TOP: 139.06,62.48 140.34,63.75 142.37,63.75 143.76,65.15 143.76,67.06 143.26,67.56 141.1,67.56 140.46,66.93 140.46,65.66 139.57,64.77 138.05,64.77 137.79,65.02 136.27,65.02 136.14,64.9 136.14,64.52 136.27,64.39 137.41,64.39 137.79,64.01 137.79,62.61 137.92,62.48
VCC5V0_USB_HOST1 on TOP: 52.73,90.12 54.86,90.12 55.12,89.87 55.12,88.7 53.77,87.35 53.77,86.21 53.47,85.9 52.91,85.9 52.35,85.34 52.35,81.92 52.2,81.76 51.49,81.76 50.42,82.83 50.09,82.83 50.09,84.51 50.98,85.39 50.98,88.37
VCC5V0_USB_HOST3 on BOTTOM: 68.31,86.86 68.15,86.69 68.15,83.92 68.38,83.69 69.37,83.69 69.62,83.44 69.62,82.8 69.65,82.78 70.36,82.78 70.41,82.83 70.41,86.36 70.92,86.87 72.39,86.87 73.15,87.63 73.15,90.17 74.3,91.31 74.3,92.08 73.91,92.46 72.39,92.46 71.88,91.95 71.88,89.03 71.25,88.39 69.9,88.39 68.36,86.86
VCC5V0_USB_OTG0 on BOTTOM: 64.52,83.69 64.52,84.84 62.23,87.12 60.88,87.12 60.48,87.53 60.48,91.67 59.21,92.94 55.4,92.94 55.02,93.32 53.75,93.32 53.39,92.96 53.39,92.18 53.67,91.9 55.14,91.9 55.45,91.59 58.5,91.59 59.11,90.98 59.11,87.5 60.88,85.72 61.44,85.72 62.23,84.94 62.23,83.69 62.36,83.57 62.36,81.66 62.48,81.53 62.99,81.53 63.12,81.66 63.12,83.19 63.37,83.44 64.26,83.44
VCC12V_DC_IN on BOTTOM: 2.16,86.23 15.11,86.23 15.37,86.49 15.37,89.28 13.72,90.93 4.7,90.93 4.06,91.57 4.06,95.12 3.68,95.5 1.27,95.5 1.14,95.38 1.14,87.25
VCC12V_DCIN on TOP: 4.95,10.29 4.95,7.75 8.64,4.06 11.3,4.06 11.43,4.19 11.43,5.08 10.03,6.48 10.03,8.89 8.51,10.41 5.08,10.41
VCC12V_DCIN on TOP: 20.73,83.72 22.56,83.72 23.14,83.13 23.14,80.67 24.08,79.73 24.08,77.42 24.69,76.81 25.55,76.81 25.93,76.43 25.93,74.9 25.86,74.83 21.18,74.83 20.09,75.92 20.09,80.92 20.73,81.56
VCC12V_DCIN on TOP: 61.85,87.5 64.26,85.09 64.26,84.2 63.75,83.69 63.75,83.06 63.25,83.06 63.25,84.33 62.74,84.84 61.34,84.84 61.09,85.09 61.09,86.49 60.54,87.03 60.55,87.05 60.55,89.2 60.93,89.59 61.8,89.59 61.85,89.53
VCC12V_DCIN on TOP: 24.1,49.96 25.02,49.96 25.32,49.66 26.04,49.66 26.04,49.05 25.98,49 25.73,49 25.12,48.39 25.12,47.32 24.89,47.09 23.62,47.09 23.37,47.35 23.37,48.82 23.55,49 23.93,49 24.1,49.17
VCC12V_DCIN on BOTTOM: 22.38,77.95 24.94,77.95 25.15,77.75 25.15,76.86 25.73,76.28 25.73,75.26 25.5,75.03 22.2,75.03 22.05,75.18 22.05,77.62
VCC12V_DCIN on VCC: 59.94,100.08 61.85,98.17 61.85,87.5 61.72,87.38 59.44,87.38 59.31,87.5 59.31,95.12 58.17,96.27 40.77,96.27 39.88,95.38 21.72,95.38 21.34,95 21.34,92.08 23.37,90.04 23.37,78.61 25.78,76.2 25.78,74.93 25.53,74.68 20.95,74.68 18.92,72.64 17.67,72.64 17.66,72.63 6.21,72.63 4.45,70.87 4.45,43.31 5.33,42.42 7.37,42.42 9.91,44.96 16.64,44.96 18.67,46.99 18.67,48.26 20.7,50.29 24.99,50.29 24.99,50.14 25.4,49.73 25.4,48.46 25.27,48.34 25.27,47.35 21.87,43.94 20.83,43.94 20.19,43.31 20.19,42.42 19.43,41.66 17.78,41.66 15.37,39.24 15.37,38.23 14.86,37.72 13.08,37.72 10.79,35.43 4.7,35.43 4.45,35.18 4.45,13.21 5.33,12.32 7.87,12.32 10.03,10.16 10.03,6.48 12.32,4.19 90.17,4.19 90.3,4.06 90.3,1.4 90.17,1.27 8,1.27 1.14,8.13 1.14,99.57 1.65,100.08
VCC_1V8 on TOP: 11.94,16.13 11.94,17.02 12.06,17.14 14.48,17.14 14.61,17.02 14.61,16.38 12.57,14.35 12.57,13.21 12.06,12.7 11.56,12.7 11.05,13.21 11.05,15.24
VCC_1V8 on TOP: 93.98,70.74 93.98,69.34 94.11,69.22 94.87,69.22 95.12,69.47 95.12,71.63 93.98,72.77 92.46,72.77 92.33,72.64 92.33,72.39
VCC_1V8 on BOTTOM: 93.34,73.53 91.06,73.53 90.93,73.41 90.93,73.15 91.06,73.03 92.08,73.03 92.33,72.77 92.33,71.75 92.46,71.63 93.22,71.63 93.47,71.88 93.47,73.41
VCC_3V3_HUB on TOP: 87,63.12 87,58.04 87.12,57.91 88.27,57.91 88.52,58.17 88.52,64.9 87.88,65.53 86.61,65.53 86.36,65.28 86.36,65.02 86.61,64.77 86.87,64.77 87.5,64.14 87.5,63.63
VCC_3V3_HUB on TOP: 78.23,52.2 77.98,52.45 77.98,57.02 78.99,58.04 78.99,60.45 78.74,60.71 76.83,60.71 75.31,62.23 74.3,62.23 74.17,62.36 74.17,63.5 74.3,63.63 75.56,63.63 76.96,62.23 83.44,62.23 84.84,60.83 84.84,59.05 84.58,58.8 83.82,58.8 82.17,60.45 81.28,60.45 81.03,60.2 81.03,52.45 80.77,52.2
VCC_3V3_HUB on BOTTOM: 86.87,59.31 87,59.44 88.27,59.44 88.39,59.31 88.39,57.15 88.27,57.02 84.58,57.02 84.45,57.15 84.45,58.42 84.2,58.67 83.82,58.67 83.69,58.8 83.69,59.44 83.95,59.69 84.33,59.69 84.71,59.31
VCC_3V8 on TOP: 124.21,37.72 125.22,37.72 125.48,37.47 125.48,35.94 125.09,35.56 124.21,35.56 124.08,35.69 124.08,37.59
VCC_3V8 on TOP: 129.16,35.18 129.16,33.15 128.4,32.38 126.87,32.38 125.73,31.24 125.73,29.46 123.95,27.69 123.95,25.02 124.08,24.89 125.22,24.89 125.35,25.02 125.35,27.05 130.05,31.75 130.05,35.18 129.92,35.31 129.29,35.31
VCC_3V8 on TOP: 117.98,37.59 117.98,33.27 118.11,33.15 118.36,33.15 118.49,33.27 118.49,35.31 119.13,35.94 119.13,37.59 119,37.72 118.11,37.72
VCC_3V8 on TOP: 125.48,19.81 125.6,19.68 126.49,19.68 126.75,19.94 127.51,19.94 127.89,20.32 127.89,21.46 127.51,21.84 125.73,21.84 125.48,21.59
VCC_3V8 on TOP: 107.82,29.21 109.47,29.21 109.6,29.34 109.6,32.64 109.35,32.89 106.81,32.89 106.55,33.15 106.55,35.69 107.31,36.45 107.31,37.47 107.19,37.59 106.17,37.59 105.92,37.34 105.92,36.32 105.54,35.94 104.52,35.94 104.39,36.07 104.39,39.12 104.14,39.37 104.14,41.27 103.89,41.53 103.07,41.53 103.07,41.5 103.02,41.45 103.02,38.66 102.9,38.53 102.87,38.53 102.87,34.16
VCC_3V8 on BOTTOM: 123.06,37.08 123.32,36.83 125.98,36.83 126.24,36.58 126.24,35.31 126.11,35.18 125.09,35.18 124.46,35.81 117.22,35.81 117.09,35.94 117.09,36.96 117.22,37.08
VCC_3V8 on BOTTOM: 127.89,31.37 130.94,31.37 131.32,31.75 131.32,33.4 131.19,33.53 130.43,33.53 130.05,33.91 127.89,33.91 127.76,33.78 127.76,31.5
VCC_3V8 on BOTTOM: 109.22,34.54 109.22,34.16 109.47,33.91 111.12,33.91 111.25,33.78 111.25,32.77 110.74,32.26 108.33,32.26 107.06,33.53 103.89,33.53 103.76,33.66 103.76,36.45 103.89,36.58 106.05,36.58 106.17,36.45 106.17,35.05 106.55,34.67 109.09,34.67
VCC_3V8 on VCC: 108.88,29.55 104.65,33.78 104.65,35.69 106.05,37.08 108.97,37.08 109.09,36.96 109.09,34.04 112.06,31.06 123.27,31.06 125.22,33.02 125.22,35.05 124.08,36.2 124.08,37.47 124.21,37.59 126.75,37.59 130.43,33.91 130.43,20.95 130.3,20.83 124.33,20.83 120.02,25.15 109.09,25.15 108.86,25.37 108.86,26.85 108.88,26.86
VCC_485 on TOP: 12.34,45.72 14.61,45.72 14.73,45.85 14.73,46.48 14.61,46.61 13.46,46.61 13.08,46.99 13.08,49.53 12.95,49.66 11.3,49.66 11.18,49.53 11.18,48.51 11.94,47.75 11.94,46.35 12.12,46.18 12.12,45.95
VCC_485 on BOTTOM: 10.67,55.12 13.34,55.12 13.46,54.99 13.46,53.98 13.34,53.85 12.45,53.85 12.19,53.59 12.19,52.2 13.97,50.42 13.97,48.77 13.84,48.64 10.67,48.64 10.41,48.9 10.41,54.86
VCC_EDP_OUT on TOP: 82.68,13.84 81.15,15.37 79.38,15.37 79.25,15.24 79.25,13.84 79.38,13.72 80.52,13.72 80.77,13.46 80.77,12.45 80.64,12.32 79.12,12.32 78.87,12.06 78.87,10.79 79.12,10.54 88.01,10.54 88.14,10.67 88.14,11.3 86.61,12.83 86.61,13.72 86.49,13.84
VCC_EDP_OUT_ on TOP: 75.06,13.72 76.33,13.72 77.09,14.48 78.11,14.48 78.23,14.35 78.23,12.45 77.34,11.56 75.18,11.56 74.93,11.81 74.93,13.59
VCC_LEDA_TX0 on TOP: 19.15,31.75 19.35,31.55 19.35,29.39 19.2,29.24 18.34,29.24 18.34,29.21 17.53,28.4 16.81,28.4 16.08,29.13 16.08,31.27 17.88,31.27 18.36,31.75
VCC_LEDA_TX0 on BOTTOM: 15.39,20.9 15.39,22.43 15.42,22.45 15.52,22.45 15.54,22.48 15.54,25.45 15.47,25.53 15.47,27.56 15.95,28.04 17.37,28.04 17.7,28.37 17.7,29.41 17.63,29.49 15.62,29.49 14.22,28.09 14.22,23.19 14.53,22.89 14.53,20.93 14.55,20.9
VCC_LEDA_TX1 on BOTTOM: 46.1,23.37 45.21,22.48 45.21,20.83 45.09,20.7 43.56,20.7 43.31,20.95 43.31,26.67 43.56,26.92 46.48,26.92 47.12,26.29 47.12,23.5 46.99,23.37
VCC_LEDK_TX0 on BOTTOM: 19.46,20.83 19.35,20.73 18.75,20.73 18.59,20.88 18.59,22.56 17.27,23.88 17.27,25.78 18.41,26.92 19.18,26.92 19.46,26.64
VCC_LEDK_TX1 on BOTTOM: 47.37,27.69 47.37,23.75 48.26,22.86 48.26,20.95 48.39,20.83 49.02,20.83 49.15,20.95 49.15,27.69 49.02,27.81 47.5,27.81
VDD10_PHY0 on BOTTOM: 99.44,68.96 97.41,68.96 97.28,68.83 97.28,67.06 97.41,66.93 99.44,66.93 99.57,67.06 99.57,68.83
VDD10_PHY0 on VCC: 99.67,75.44 99.93,75.69 109.24,75.69 109.54,75.4 109.54,68.4 109.27,68.14 107.27,68.14 106.87,68.53 106.87,70.69 105.87,71.69 103.84,71.69 103.7,71.83 103.7,72.18 104.46,72.95 104.46,73.74 103.96,74.23 102.28,74.23 100.2,72.15 100.2,66.93 100.08,66.8 97.54,66.8 97.41,66.93 97.41,75.18 97.66,75.44
VDD10_PHY1 on TOP: 112.39,67.06 114.43,67.06 114.55,66.93 114.55,66.29 114.43,66.17 112.39,66.17 112.27,66.29 112.27,66.93
VDD10_PHY1 on BOTTOM: 115.32,66.93 115.19,67.06 113.54,67.06 113.41,66.93 113.41,64.39 113.54,64.26 115.19,64.26 115.32,64.39
VDD10_PHY1 on VCC: 123.14,65.98 120.98,68.14 116.76,68.14 116.14,67.52 116.14,66.63 115.62,66.1 112.84,66.1 112.84,70.66 113.24,71.06 118.7,71.06 119.19,71.55 119.19,72.06 119.59,72.45 121.84,72.45 122.24,72.06 122.24,71.17 123.76,69.64 123.76,66.12 123.62,65.98
VDD_3V3 on TOP: 71.63,58.67 59.94,58.67 59.23,59.39 55.65,59.39 55.3,59.03 54.03,59.03 52.91,57.91 36.83,57.91 36.7,58.04 36.7,59.05 37.47,59.82 40.13,59.82 40.64,60.33 71.5,60.33 72.01,59.82 72.01,59.05
VDD_3V3 on TOP: 93.34,17.27 93.34,16.26 93.47,16.13 94.49,16.13 94.74,16.38 95.63,16.38 95.76,16.51 95.76,17.65 95.63,17.78 93.85,17.78
VDD_3V3 on TOP: 124.97,63.55 124.97,60.5 125.12,60.35 125.2,60.35 125.22,60.33 127.89,60.33 128.02,60.45 128.02,61.85 127.89,61.98 127.25,61.98 127,62.23 127,62.66 127.25,62.92 128.22,62.92 128.27,62.97 128.27,63.6 128.18,63.69 126.05,63.69 126.03,63.7 125.12,63.7
VDD_3V3 on TOP: 126.62,54.99 125.35,54.99 125.22,54.86 125.22,53.72 125.35,53.59 126.62,53.59 126.75,53.72 126.75,54.86
VDD_3V3 on TOP: 58.29,12.7 58.29,11.68 58.17,11.56 55.5,11.56 55.24,11.81 55.24,14.22 55.37,14.35 56.52,14.35 56.77,14.1 56.77,13.08 56.9,12.95 58.04,12.95
VDD_3V3 on BOTTOM: 23.5,70.48 18.67,70.48 18.54,70.61 18.54,72.01 18.67,72.14 23.37,72.14 28.32,77.09 28.83,77.09 28.96,76.96 28.96,75.95
VDD_3V3 on BOTTOM: 93.09,20.57 94.11,20.57 94.36,20.32 94.36,19.05 95.5,17.91 95.5,16.64 95.25,16.38 94.49,16.38 94.23,16.64 94.23,17.02 92.84,18.41 92.84,18.67 91.69,19.81 91.69,22.35 91.95,22.61 92.46,22.61 92.84,22.23 92.84,20.83
VDD_3V3 on BOTTOM: 88.39,55.63 87.63,54.86 86.87,54.86 86.74,54.99 86.74,56.64 86.87,56.77 88.27,56.77 88.39,56.64
VDD_3V3 on BOTTOM: 82.42,18.8 83.69,17.53 83.69,16.76 83.44,16.51 80.77,16.51 80.52,16.76 80.52,25.4 78.87,27.05 76.2,27.05 76.07,27.18 76.07,27.94 75.82,28.19 70.61,28.19 68.71,30.1 67.56,30.1 67.18,30.48 67.18,31.62 67.69,32.13 67.69,35.94 68.45,36.7 68.45,37.97 68.83,38.35 68.83,40.13 68.96,40.26 70.1,40.26 72.77,42.93 72.77,58.67 70.36,58.67 70.1,58.93 70.1,60.33 70.61,60.83 71.75,60.83 74.17,58.42 74.17,41.15 69.85,36.83 69.85,34.29 70.1,34.04 70.1,31.37 71.5,29.97 76.71,29.97 77.85,28.83 79.5,28.83 79.76,28.57 79.88,28.57 81.53,26.92 81.53,24 82.42,23.11
VDD_3V3 on BOTTOM: 21.34,48.9 22.12,48.9 22.12,48.79 22.28,48.64 22.28,48.06 21.84,47.62 21.84,46.61 21.72,46.48 20.07,46.48 19.94,46.61 19.94,47.75 20.19,48.01 20.19,50.04 17.65,52.58 17.65,54.86 17.78,54.99 19.05,54.99 19.18,54.86 19.18,52.45 21.21,50.42 21.21,49.02
VDD_3V3 on BOTTOM: 33.07,20.24 33.07,23.01 33.16,23.1 33.16,25.67 33.66,26.16 33.66,26.7 33.38,26.97 33.07,26.97 32.92,27.13 32.92,27.58 33.07,27.74 33.53,27.74 33.55,27.71 35.28,27.71 35.43,27.56 35.43,26.8 34.42,25.78 34.42,18.29 33.27,17.14 33.27,14.61 33.4,14.48 41.27,14.48 45.47,18.67 61.59,18.67 62.36,19.43 62.36,20.32 62.87,20.83 62.87,25.65 62.99,25.78 62.99,30.99 59.69,34.29 59.69,40.36 59.97,40.64 59.97,41.55 60.58,42.16 64.64,42.16 64.77,42.04 64.77,41.66 64.64,41.53 63.63,41.53 63.37,41.27 63.37,35.43 63.25,35.31 62.61,35.31 62.36,35.05 62.36,34.42 62.48,34.29 64.14,34.29 65.02,33.4 65.02,17.4 65.15,17.27 66.8,17.27 66.93,17.14 66.93,15.37 64.39,12.83 56.52,12.83 53.85,15.49 47.75,15.49 45.21,12.95 31.24,12.95 31.11,13.08 31.11,18.29
VDD_3V3 on BOTTOM: 88.9,73.53 88.77,73.66 88.77,74.93 89.92,76.07 90.55,76.07 90.93,75.69 91.57,75.69 91.69,75.82 91.69,76.71 91.44,76.96 89.66,76.96 87.76,75.06 87.76,71.88 89.41,70.23 90.93,70.23 92.08,71.37 92.08,72.52 91.82,72.77 91.06,72.77 90.81,72.52 90.81,72.14 90.55,71.88 90.04,71.88 89.79,72.14 89.79,73.41 89.66,73.53
VDD_3V3 on BOTTOM: 35.56,55.37 32,55.37 31.88,55.5 31.88,56.01 32,56.13 35.56,56.13 35.69,56.26 35.69,56.64 35.56,56.77 34.8,56.77 34.67,56.9 34.67,57.4 34.92,57.66 35.56,57.66 35.69,57.78 35.69,59.18 35.56,59.31 34.54,59.31 34.29,59.05 32,59.05 31.88,59.18 31.88,59.82 32.51,60.45 34.54,60.45 34.67,60.58 34.67,61.21 34.8,61.34 35.56,61.34 35.69,61.47 35.69,62.87 35.56,62.99 34.16,62.99 33.91,62.74 32,62.74 31.88,62.87 31.88,63.37 32,63.5 33.53,63.5 34.16,64.14 38.1,64.14 38.35,63.88 38.35,46.86 36.7,45.21 35.69,45.21 35.56,45.34 35.56,50.55 35.05,51.05 33.53,51.05 33.4,51.18 33.4,52.45 33.53,52.58 34.54,52.58 34.67,52.7 34.67,53.59 34.8,53.72 35.43,53.72 35.69,53.98 35.69,55.24
VDD_3V3 on VCC: outline of 90 points within 10.54,38.35 130.43,75.31
VDD_LVDS on TOP: 18.75,20.42 19.51,20.42 19.56,20.37 19.56,19.91 19.43,19.79 19.43,18.47 19.51,18.39 20.02,18.39 20.17,18.54 20.17,19.53 20.22,19.58 20.5,19.58 20.57,19.51 20.57,18.44 19.28,17.14 14.86,17.14 14.61,17.4 13.46,17.4 13.34,17.53 13.34,18.29 13.46,18.41 14.48,18.41 14.99,17.91 18.16,17.91 18.54,18.29 18.54,18.54 18.59,18.59 18.59,20.27
VDD_USB_5V on TOP: 85.45,82.52 85.45,83.11 85.04,83.52 80.37,83.52 80.01,83.16 80.01,82.55 80.29,82.27 85.19,82.27
VDD_USB_5V on TOP: 134.49,64.14 134.49,61.85 134.37,61.72 133.1,61.72 132.97,61.85 132.97,66.8 133.22,67.06 134.62,67.06 134.75,66.93 134.75,64.39
VDD_USB_5V on TOP: 94.61,80.52 97.66,80.52 97.79,80.64 97.79,82.3 97.66,82.42 96.39,82.42 95.63,81.66 94.61,81.66 94.49,81.53 94.49,80.64
VDD_USB_5V on TOP: 134.49,52.07 134.37,51.94 133.22,51.94 133.1,52.07 133.1,55.12 133.22,55.24 134.49,55.24 134.62,55.12 134.62,53.85 134.49,53.72
VDD_USB_5V on TOP: 134.37,43.94 134.37,42.8 134.24,42.67 133.1,42.67 132.59,43.18 132.59,45.09 132.84,45.34 134.62,45.34 134.75,45.21 134.75,44.32
VDD_USB_5V on TOP: 50.93,79.12 50.55,78.74 49.66,78.74 49.53,78.87 49.53,81.41 49.78,81.66 50.8,81.66 50.93,81.53
VDD_USB_5V on TOP: 55.88,84.96 59.18,84.96 59.44,84.71 59.44,80.9 59.31,80.77 56.39,80.77 56.13,81.03 56.13,81.28 55.88,81.53
VDD_USB_5V on BOTTOM: 81.74,83.26 86.51,83.26 86.92,82.85 86.92,82.09 86.69,81.86 84.02,81.86 83.46,82.42 81.76,82.42 81.66,82.52 81.66,83.19
VDD_USB_5V on BOTTOM: 65.66,80.26 67.69,80.26 68.33,80.9 69.34,80.9 69.72,81.28 70.36,81.28 70.87,80.77 70.87,79.25 72.77,77.34 72.77,75.44 72.52,75.18 69.72,75.18 69.09,75.82 69.09,77.65 68.5,78.23 56.9,78.23 56.13,78.99 56.13,85.47 56.26,85.6 58.8,85.6 58.93,85.47 58.93,80.39 59.31,80.01 63.37,80.01 63.63,80.26 63.63,81.92 63.75,82.04 64.39,82.04 64.52,81.92 64.52,81.41
